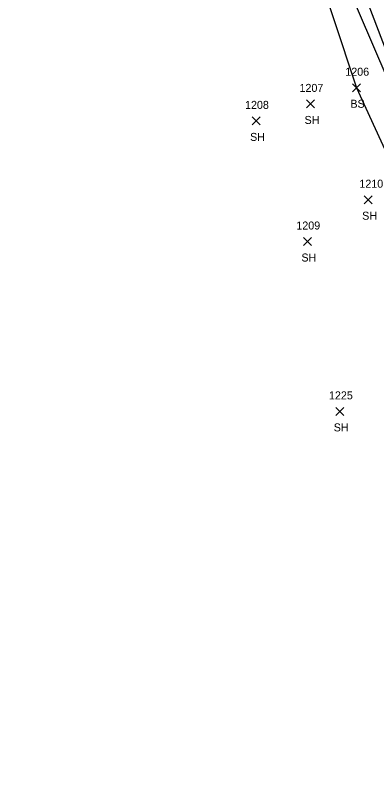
# Model space of a CAD drawing. Extents: x 1651305 to 1654558, y 539481 to 548441.
# Drawn here: x 1654112.9 to 1654203, y 544748.1 to 544943.1 of the extents above; entities that cross this region are included whole.
import ezdxf

# ---------------------------------------------------------------- set-up
doc = ezdxf.new("R2010")
doc.units = 0
for name, color, linetype in [('L_A', 7, 'Continuous'), ('L_I', 7, 'Continuous'), ('L_TIC', 7, 'Continuous'), ('LELB', 7, 'Continuous'), ('PET', 7, 'Continuous')]:
    doc.layers.add(name, color=color, linetype=linetype)

msp = doc.modelspace()

# ---------------------------------------------------------------- linework, layer by layer
at = {"layer": 'L_TIC'}
for points in [[(1654197.08, 544924.07), (1654199.08, 544926.07)], [(1654199.08, 544924.07), (1654197.08, 544926.07)], [(1654185.58, 544920.03), (1654187.58, 544922.03)], [(1654187.58, 544920.03), (1654185.58, 544922.03)], [(1654171.97, 544915.79), (1654173.97, 544917.79)], [(1654173.97, 544915.79), (1654171.97, 544917.79)], [(1654199.98, 544896.1), (1654201.98, 544898.1)], [(1654201.98, 544896.1), (1654199.98, 544898.1)], [(1654184.8, 544885.66), (1654186.8, 544887.66)], [(1654186.8, 544885.66), (1654184.8, 544887.66)], [(1654192.86, 544843.23), (1654194.86, 544845.23)], [(1654194.86, 544843.23), (1654192.86, 544845.23)]]:
    msp.add_lwpolyline(points, dxfattribs=at)
at = {"layer": 'LELB'}
for points in [[(1654179.72, 544986.88), (1654191.76, 544959.88), (1654205.63, 544927.6), (1654216.28, 544901.81), (1654236.78, 544849.69), (1654250.25, 544817.94), (1654269.19, 544772.35), (1654285.71, 544732), (1654294.18, 544708.03), (1654311.84, 544664.34)], [(1654177.71, 544985.41), (1654186.4, 544960.29), (1654198.08, 544925.07), (1654208.78, 544901.64), (1654231.34, 544847.61), (1654245.85, 544816.46), (1654261.74, 544769.7), (1654274.87, 544730.83), (1654284.44, 544695.19), (1654297.61, 544656.98), (1654309.41, 544642.27)]]:
    msp.add_lwpolyline(points, dxfattribs=at)
at = {"layer": 'PET'}
msp.add_lwpolyline([(1654112.87, 545166.54), (1654122.04, 545140.21), (1654132.62, 545111.94), (1654135.36, 545108.19), (1654138.44, 545103.48), (1654151.39, 545069.68), (1654150.58, 545065.43), (1654160.56, 545041.12), (1654174.1, 545006.91), (1654181.29, 544989.93), (1654184.89, 544987.01), (1654195.03, 544961.54), (1654207.76, 544928.16), (1654222.99, 544890.41), (1654239.03, 544850.69), (1654252.07, 544818.68), (1654270.72, 544773.03), (1654287.36, 544732.43), (1654297.76, 544708.46), (1654313.88, 544667.1), (1654319.77, 544684.6), (1654325.71, 544702.64)], dxfattribs=at)

# ---------------------------------------------------------------- texts
at = {"layer": 'L_A'}
for s, p in [('BS', (1654196.52, 544920.07)), ('SH', (1654185.07, 544916.03)), ('SH', (1654171.46, 544911.79)), ('SH', (1654199.47, 544892.1)), ('SH', (1654184.29, 544881.66)), ('SH', (1654192.35, 544839.23))]:
    msp.add_text(s, height=2, dxfattribs=at).set_placement(p)
at = {"layer": 'L_I'}
for s, p in [('1206', (1654195.25, 544928.07)), ('1207', (1654183.81, 544924.03)), ('1208', (1654170.2, 544919.79)), ('1210', (1654198.77, 544900.1)), ('1209', (1654183.02, 544889.66)), ('1225', (1654191.17, 544847.23))]:
    msp.add_text(s, height=2, dxfattribs=at).set_placement(p)

doc.saveas('drawing.dxf')
